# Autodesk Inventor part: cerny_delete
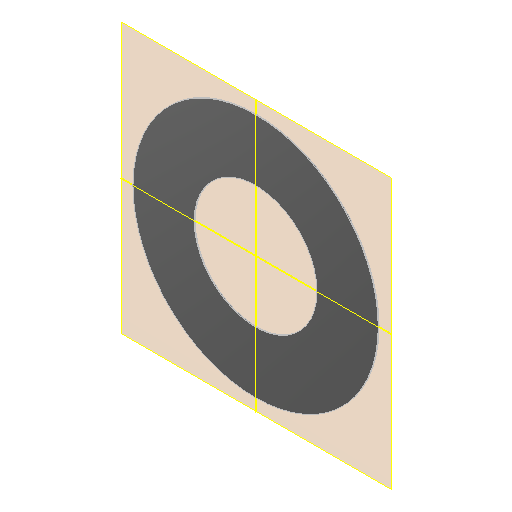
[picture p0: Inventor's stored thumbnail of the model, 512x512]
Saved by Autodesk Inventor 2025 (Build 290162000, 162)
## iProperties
Created: 2025-03
Part Number: cerny_delete
Material: UHMW, Black
Document SubType Name: Modeling
Designer: dansp
Mass: 4.98335e-05 g
Surface Area: 0.107442 cm^2
Volume: 5.30144e-05 cm^3
Density: 0.94 g/cm^3
Appearance: Smooth - Black
Author: dansp
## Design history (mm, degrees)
sketch "Sketch1"
  geometry: C1 r 1.5 at (0, 0); C2 r 0.75 at (0, 0); 1 further point
  constraints: 2 centre point, 2 coincident
  dimensions: "d0" = 3 diameter of C1; "d1" = 1.5 diameter of C2
extrude "Extrusion1" new body sketch "Sketch1" distance "d2" = 0.01; taper "d3" = 0 deg
body "Solid1"
